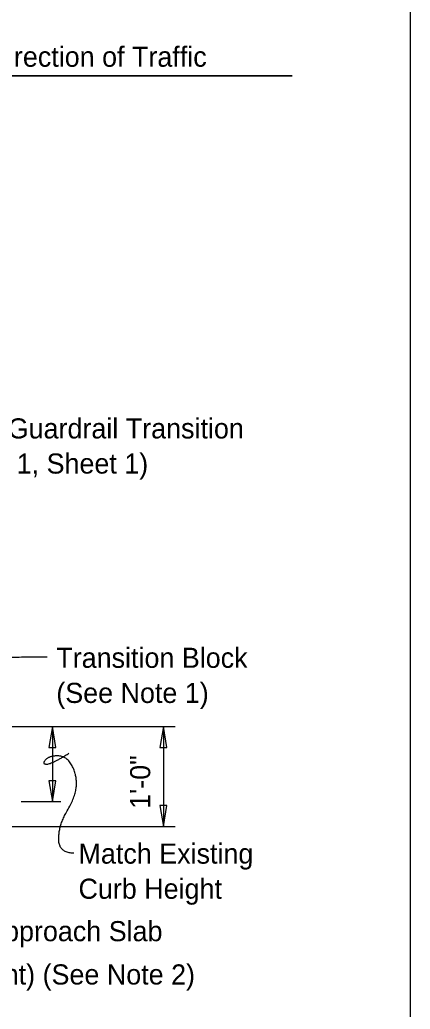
# Model space of a CAD drawing. Extents: x 21526.6 to 21595.9, y 56114.9 to 56157.2.
# Drawn here: x 21541.8 to 21545.72, y 56132.38 to 56142.29 of the extents above; entities that cross this region are included whole.
import ezdxf

# ---------------------------------------------------------------- set-up
doc = ezdxf.new("R2010")
doc.units = 0
doc.layers.add('Border', color=7, linetype='Continuous')
doc.layers.add('PlotBorder_dp', color=7, linetype='Continuous')

msp = doc.modelspace()

# ---------------------------------------------------------------- linework, layer by layer
at = {"layer": 'PlotBorder_dp'}
for p, q in [((21545.7163, 56153.2556), (21545.7163, 56127.3172)), ((21544.4067, 56141.7314), (21540.5963, 56141.7314)), ((21541.3196, 56141.7314), (21544.533, 56141.7314)), ((21544.533, 56141.7314), (21544.4067, 56141.7314)), ((21539.8821, 56135.2101), (21543.3608, 56135.2101)), ((21542.129, 56135.2101), (21542.129, 56134.4601)), ((21543.2414, 56135.2102), (21543.2414, 56134.2102)), ((21541.8169, 56134.4601), (21542.2116, 56134.4601)), ((21539.8821, 56134.2101), (21543.3608, 56134.2101))]:
    msp.add_line(p, q, dxfattribs=at)
for points in [[(21542.129, 56135.2101), (21542.0937, 56135.0018), (21542.1642, 56135.0018)], [(21543.2414, 56135.2102), (21543.2061, 56135.0019), (21543.2766, 56135.0019)], [(21542.129, 56134.4601), (21542.1642, 56134.6683), (21542.0937, 56134.6683)], [(21543.2414, 56134.2102), (21543.2766, 56134.4184), (21543.2061, 56134.4184)]]:
    msp.add_lwpolyline(points, close=True, dxfattribs=at)
for points in [[(21542.0754, 56135.9047), (21541.4139, 56135.9116), (21541.1398, 56135.7744), (21540.9568, 56135.6032), (21540.7613, 56135.3058), (21540.7613, 56135.0162), (21540.2137, 56134.8128), (21539.7444, 56134.8049)], [(21542.3427, 56133.9425), (21542.1919, 56133.9425), (21542.1919, 56134.2238), (21542.3701, 56134.5256), (21542.3701, 56134.7451), (21542.2673, 56134.9166), (21542.0959, 56134.9166), (21542.0206, 56134.8343), (21542.1234, 56134.8343), (21542.2947, 56134.944)]]:
    msp.add_open_spline(points, degree=2, dxfattribs=at)

# ---------------------------------------------------------------- texts
at = {"layer": 'Border'}
for s, rotation, p in [('Direction of Traffic', 359.99977, (21541.4883, 56141.8217)), ('1\'-0"', 90, (21543.1097, 56134.3857))]:
    msp.add_text(s, height=0.2016, rotation=rotation, dxfattribs=at).set_placement(p)
for s, p in [('Existing Approach Slab', (21540.4455, 56133.0596)), ('Dowel Bars 4L (10" Embedment) (See Note 2)', (21538.0238, 56132.6259))]:
    msp.add_text(s, height=0.2016, dxfattribs=at).set_placement(p)
at = {"layer": 'PlotBorder_dp'}
for s, p in [('Roadway Guardrail Transition', (21540.4819, 56138.0972)), ('(See Note 1, Sheet 1)', (21540.4819, 56137.7452)), ('Transition Block', (21542.1678, 56135.799)), ('(See Note 1)', (21542.1678, 56135.447)), ('Match Existing ', (21542.3904, 56133.8368)), ('Curb Height', (21542.3904, 56133.4848))]:
    msp.add_text(s, height=0.2016, dxfattribs=at).set_placement(p)

doc.saveas('drawing.dxf')
